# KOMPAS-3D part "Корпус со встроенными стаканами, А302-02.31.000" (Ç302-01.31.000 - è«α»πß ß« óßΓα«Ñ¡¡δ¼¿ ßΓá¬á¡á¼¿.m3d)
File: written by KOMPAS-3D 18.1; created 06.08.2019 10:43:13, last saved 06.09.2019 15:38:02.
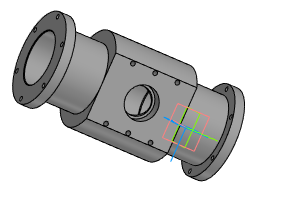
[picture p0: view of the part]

Document properties: Автор: Пользователь Windows; Полное имя файла: D:\Мембранные насосы\Мембранный электропривод\А302-00.00.000 - ASTRA-302 (МЭ200)\3Д ПВХ\А302-01.31.000 - Корпус со встроенными стаканами.m3d

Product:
- Part/product: Корпус со встроенными стаканами  | designation А302-02.31.000  | pos. 2
    Материал: Поливинилхлорид (density 1350 kg/m3)
    Масса: 3.18846
    source file: ..\Чертежи ПВХ\А302-02.31.000 - Корпус со встроенными стаканами.cdw, А302-02.00.000 - ASTRA-302 (МЭ200)\А302-02.31.000 - Корпус со встроенными стаканами.cdw
  - Body: (unnamed)
      Масса: 3.54993
  - Body: Тело 18
      Масса: 3.54993
  - Body: Тело 19
      Масса: 3.54993
- Part/product: Корпус со встроенными стаканами  | designation А302-01.31.000
    Материал: Поливинилхлорид (density 1350 kg/m3)
    Масса: 2.63451
- Part/product: Корпус со встроенными стаканами  | designation А302-03.31.000  | pos. 2
    Материал: Поливинилхлорид (density 1350 kg/m3)
    Масса: 2.60942
    source file: ..\..\А302-03.00.000 - ASTRA-302 (МЭ200)\А302-03.31.000 - Корпус со встроенными стаканами.cdw, ..\Чертежи Полипропилен\А302-03.31.000 - Корпус со встроенными стаканами.cdw
  - Body: Тело 19
      Масса: 3.54993
  - Body: Тело 18
      Масса: 3.54993
  - Body: (unnamed)
      Масса: 3.54993

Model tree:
1. Эскиз:2  (labels: А302-01.11.000 - Крышка рабочей камеры.a3d)
2. Элемент выдавливания:1
     Расстояние 1 = 225; Расстояние 2 = 10
3. Эскиз:8  (with: Элемент выдавливания:1)
4. Элемент выдавливания:3
     Расстояние 2 = 55
5. Эскиз:10  (with: Элемент выдавливания:1)
6. Элемент выдавливания:4
     Расстояние 2 = 55
7. Эскиз:12  (with: Элемент выдавливания:3)
8. Элемент выдавливания:5
     Расстояние 2 = 170
9. Эскиз:20  (with: Элемент выдавливания:1)
10. Элемент выдавливания:7
     Расстояние 2 = 225
11. Эскиз:22  (with: Элемент выдавливания:3, Элемент выдавливания:1)
12. Элемент выдавливания:8
     Расстояние 2 = 20
13. Эскиз:24  (with: Элемент выдавливания:4, Элемент выдавливания:8)
14. Элемент выдавливания:9
     Расстояние 1 = 20
15. Эскиз:26  (with: Элемент выдавливания:7)
16. Элемент выдавливания:10
     Расстояние 2 = 25
17. Эскиз:28  (with: Элемент выдавливания:10)
18. Элемент выдавливания:11  (labels: А302-01.11.000 - Крышка рабочей камеры.a3d)
     Расстояние 2 = 30
19. Эскиз:42  (with: Элемент выдавливания:1, Элемент выдавливания:3)
20. Элемент выдавливания:18
     Расстояние 2 = 15
21. Эскиз:48  (with: Элемент выдавливания:1, Операция вращения:1)
22. Элемент выдавливания:21
     Расстояние 2 = 15
23. Эскиз:50  (with: Элемент выдавливания:21, Элемент выдавливания:1)
24. Элемент выдавливания:22
     Расстояние 2 = 15
25. Эскиз:52  (with: Операция вращения:1, Элемент выдавливания:1)  (labels: А302-01.11.000 - Крышка рабочей камеры.a3d)
26. Элемент выдавливания:23
     Расстояние 2 = 15
27. Эскиз:54  (with: Элемент выдавливания:23, Элемент выдавливания:1)
28. Элемент выдавливания:24
     Расстояние 2 = 15
29. Эскиз:56  (with: Элемент выдавливания:1, Элемент выдавливания:18, Элемент выдавливания:22)
30. Элемент выдавливания:25
     Расстояние 2 = 15
31. Эскиз:62  (with: Элемент выдавливания:24, Элемент выдавливания:27)
32. Элемент выдавливания:29  (with: Элемент выдавливания:22)
     Расстояние 2 = 221
33. Элемент выдавливания:32  (with: Элемент выдавливания:24)
     Расстояние 2 = 21.5
34. Элемент выдавливания:33  (with: Элемент выдавливания:22)
     Расстояние 2 = 21.5
35. Элемент выдавливания:36  (with: Элемент выдавливания:32)
     Расстояние 1 = 10
36. Элемент выдавливания:37  (with: Элемент выдавливания:33)
     Расстояние 1 = 10
37. Фаска:1  (with: Элемент выдавливания:3, Элемент выдавливания:4)
     Угол = 45; Длина 1 = 1; Длина 2 = 1
38. Фаска:2  (with: Элемент выдавливания:5)
     Угол = 45; Длина 1 = 3; Длина 2 = 3
39. Эскиз:74  (labels: А302-01.11.000 - Крышка рабочей камеры.a3d)
40. Элемент выдавливания:39
     Расстояние 1 = 265
41. Эскиз:76  (with: Элемент выдавливания:39)
42. Эскиз:78  (with: Элемент выдавливания:1)  (labels: Труба PVC-U 50*3,7)
43. Фаска:6  (with: Элемент выдавливания:39)
     Угол = 15; Длина 1 = 3; Длина 2 = 0.803848
44. Эскиз:80  (with: Элемент выдавливания:39)
45. Элемент выдавливания:42
     Расстояние 2 = 15
46. Эскиз:82  (with: Элемент выдавливания:42)
47. Элемент выдавливания:43
     Расстояние 2 = 17
48. Фаска:7  (with: Элемент выдавливания:42)  (labels: А302-01.11.000 - Крышка рабочей камеры.a3d)
     Угол = 15; Длина 1 = 3; Длина 2 = 0.803848
49. Эскиз:84  (with: Элемент выдавливания:1)
50. Эскиз:86  (with: Элемент выдавливания:1, Элемент выдавливания:2)
51. Элемент выдавливания:45
     Расстояние 1 = 23
52. Эскиз:88  (with: Элемент выдавливания:45)
53. Элемент выдавливания:46
     Расстояние 2 = 28
54. Эскиз:99  (with: Элемент выдавливания:24, Элемент выдавливания:22)  (labels: А302-01.11.000 - Крышка рабочей камеры.a3d)
55. Элемент выдавливания:53
     Расстояние 1 = 70; Расстояние 2 = 70
56. Смещенная плоскость:1
     Расстояние = 145
57. Эскиз:106
58. Элемент выдавливания:57
     Расстояние 1 = 37.5333
59. Эскиз:115  (with: Элемент выдавливания:53)
60. Элемент выдавливания:60
     Расстояние 2 = 17
61. Эскиз:116  (with: Элемент выдавливания:53)
62. Элемент выдавливания:61
     Расстояние 2 = 121

Referenced files in D:\Мембранные насосы\Мембранный электропривод\А302-00.00.000 - ASTRA-302 (МЭ200)\3Д ПВХ\: А302-01.11.000 - Крышка рабочей камеры.a3d
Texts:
  Точка начала. Х
  Точка начала. Y
  Точка начала. Z
  Крышка рабочей камеры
